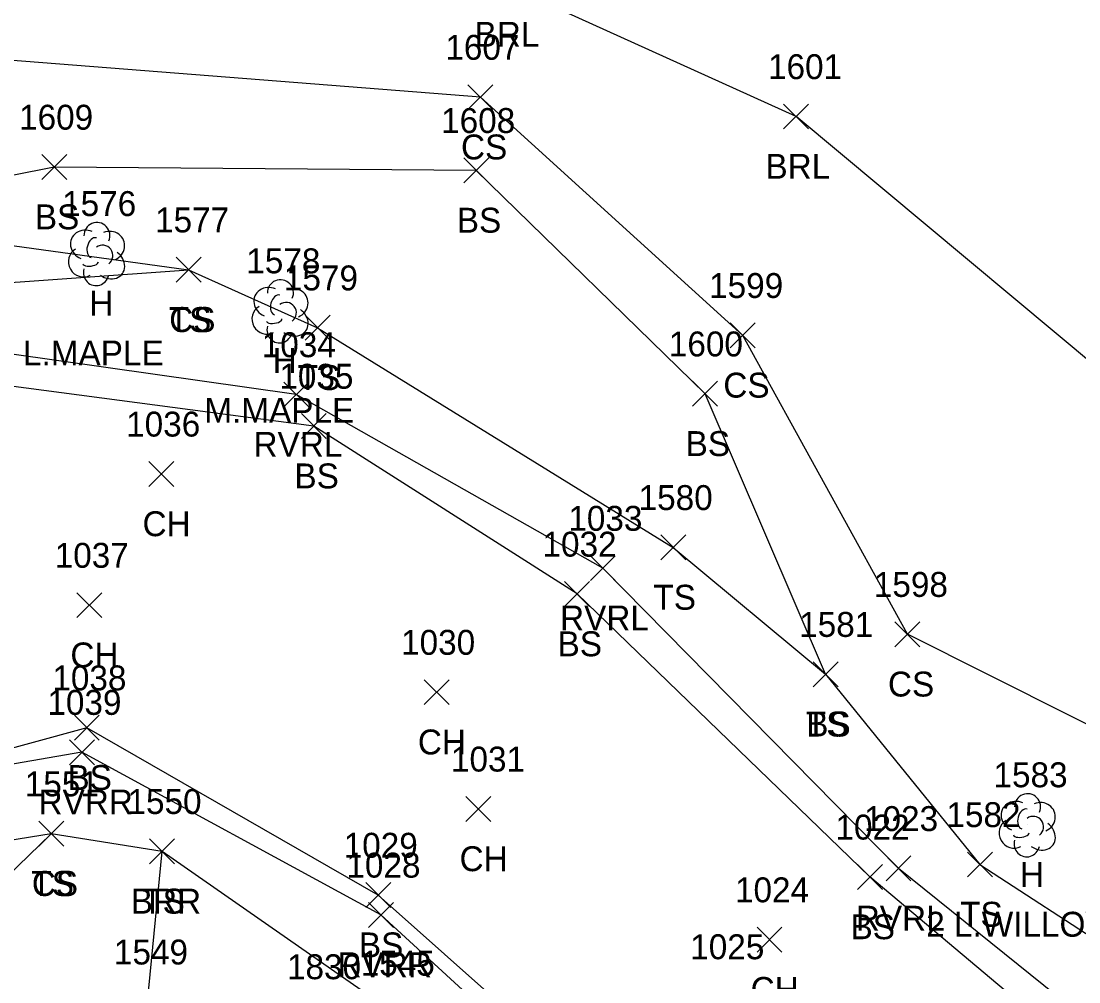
# Model space of a CAD drawing. Extents: x 1469310 to 1475157, y 493997 to 498873.
# Drawn here: x 1469623 to 1469708, y 498574.2 to 498651.4 of the extents above; entities that cross this region are included whole.
import ezdxf

# ---------------------------------------------------------------- set-up
doc = ezdxf.new("R2010")
doc.units = 0
for name, color, linetype in [('L_A', 7, 'Continuous'), ('L_C', 7, 'Continuous'), ('L_I', 7, 'Continuous'), ('L_TIC', 7, 'Continuous'), ('LABL', 7, 'Continuous'), ('LAWE', 7, 'Continuous'), ('LELB', 7, 'Continuous'), ('LTD', 7, 'Continuous')]:
    doc.layers.add(name, color=color, linetype=linetype)

msp = doc.modelspace()

# ---------------------------------------------------------------- linework, layer by layer
at = {"layer": 'L_TIC'}
for points in [[(1469658.92, 498644.282), (1469660.92, 498646.282)], [(1469660.92, 498644.282), (1469658.92, 498646.282)], [(1469684.262, 498642.727), (1469686.262, 498644.727)], [(1469686.262, 498642.727), (1469684.262, 498644.727)], [(1469624.704, 498638.67), (1469626.704, 498640.67)], [(1469626.704, 498638.67), (1469624.704, 498640.67)], [(1469658.583, 498638.402), (1469660.583, 498640.402)], [(1469660.583, 498638.402), (1469658.583, 498640.402)], [(1469635.49, 498630.421), (1469637.49, 498632.421)], [(1469637.49, 498630.421), (1469635.49, 498632.421)], [(1469635.49, 498630.421), (1469637.49, 498632.421)], [(1469637.49, 498630.421), (1469635.49, 498632.421)], [(1469645.843, 498625.766), (1469647.843, 498627.766)], [(1469647.843, 498625.766), (1469645.843, 498627.766)], [(1469679.981, 498625.156), (1469681.981, 498627.156)], [(1469681.981, 498625.156), (1469679.981, 498627.156)], [(1469644.136, 498620.402), (1469646.136, 498622.402)], [(1469646.136, 498620.402), (1469644.136, 498622.402)], [(1469676.953, 498620.464), (1469678.953, 498622.464)], [(1469678.953, 498620.464), (1469676.953, 498622.464)], [(1469645.545, 498617.868), (1469647.545, 498619.868)], [(1469647.545, 498617.868), (1469645.545, 498619.868)], [(1469633.302, 498614.028), (1469635.302, 498616.028)], [(1469635.302, 498614.028), (1469633.302, 498616.028)], [(1469674.4, 498608.126), (1469676.4, 498610.126)], [(1469676.4, 498608.126), (1469674.4, 498610.126)], [(1469668.748, 498606.461), (1469670.748, 498608.461)], [(1469670.748, 498606.461), (1469668.748, 498608.461)], [(1469666.675, 498604.387), (1469668.675, 498606.387)], [(1469668.675, 498604.387), (1469666.675, 498606.387)], [(1469627.511, 498603.492), (1469629.511, 498605.492)], [(1469629.511, 498603.492), (1469627.511, 498605.492)], [(1469693.201, 498601.154), (1469695.201, 498603.154)], [(1469695.201, 498601.154), (1469693.201, 498603.154)], [(1469686.639, 498597.943), (1469688.639, 498599.943)], [(1469688.639, 498597.943), (1469686.639, 498599.943)], [(1469686.639, 498597.943), (1469688.639, 498599.943)], [(1469688.639, 498597.943), (1469686.639, 498599.943)], [(1469655.408, 498596.505), (1469657.408, 498598.505)], [(1469657.408, 498596.505), (1469655.408, 498598.505)], [(1469627.321, 498593.647), (1469629.321, 498595.647)], [(1469629.321, 498593.647), (1469627.321, 498595.647)], [(1469626.93, 498591.682), (1469628.93, 498593.682)], [(1469628.93, 498591.682), (1469626.93, 498593.682)], [(1469658.757, 498587.13), (1469660.757, 498589.13)], [(1469660.757, 498587.13), (1469658.757, 498589.13)], [(1469624.46, 498585.142), (1469626.46, 498587.142)], [(1469626.46, 498585.142), (1469624.46, 498587.142)], [(1469624.46, 498585.142), (1469626.46, 498587.142)], [(1469626.46, 498585.142), (1469624.46, 498587.142)], [(1469633.36, 498583.722), (1469635.36, 498585.722)], [(1469635.36, 498583.722), (1469633.36, 498585.722)], [(1469633.36, 498583.722), (1469635.36, 498585.722)], [(1469635.36, 498583.722), (1469633.36, 498585.722)], [(1469692.491, 498582.351), (1469694.491, 498584.351)], [(1469694.491, 498582.351), (1469692.491, 498584.351)], [(1469699.03, 498582.669), (1469701.03, 498584.669)], [(1469701.03, 498582.669), (1469699.03, 498584.669)], [(1469690.198, 498581.668), (1469692.198, 498583.668)], [(1469692.198, 498581.668), (1469690.198, 498583.668)], [(1469650.721, 498580.21), (1469652.721, 498582.21)], [(1469652.721, 498580.21), (1469650.721, 498582.21)], [(1469650.931, 498578.614), (1469652.931, 498580.614)], [(1469652.931, 498578.614), (1469650.931, 498580.614)], [(1469682.129, 498576.632), (1469684.129, 498578.632)], [(1469684.129, 498576.632), (1469682.129, 498578.632)]]:
    msp.add_lwpolyline(points, dxfattribs=at)
at = {"layer": 'LABL'}
for points in [[(1469804.951, 498565.122), (1469764.815, 498561.657), (1469749.085, 498576.217), (1469733.116, 498600.55), (1469716.502, 498617.668), (1469685.262, 498643.727), (1469661.907, 498654.328), (1469615.65, 498657.999), (1469588.273, 498643.441), (1469563.61, 498633.273)], [(1469812.399, 498427.833), (1469789.823, 498450.509), (1469762.155, 498470.412), (1469730.759, 498496.59), (1469695.428, 498518.468), (1469668.132, 498535.818), (1469658.486, 498545.191), (1469647.104, 498565.825), (1469633.195, 498572.637), (1469634.36, 498584.722)]]:
    msp.add_lwpolyline(points, dxfattribs=at)
at = {"layer": 'LAWE'}
for points in [[(1469773.599, 498538.143), (1469743.152, 498547.619), (1469721.093, 498561.124), (1469693.491, 498583.351), (1469669.748, 498607.461), (1469645.136, 498621.402), (1469610.764, 498626.27), (1469594.257, 498621.311), (1469595.404, 498613.659), (1469596.705, 498614.177)], [(1469777.093, 498513.113), (1469746.487, 498519.646), (1469712.258, 498538.306), (1469693.077, 498549.784), (1469666.06, 498566.648), (1469651.931, 498579.614), (1469627.93, 498592.682), (1469614.452, 498590.358), (1469606.528, 498592.025), (1469606.275, 498594.975), (1469607.183, 498595.593)]]:
    msp.add_lwpolyline(points, dxfattribs=at)
at = {"layer": 'LELB'}
for points in [[(1469749.085, 498576.217), (1469720.606, 498588.908), (1469694.201, 498602.154), (1469680.981, 498626.156), (1469659.92, 498645.282), (1469619.31, 498648.468), (1469591.689, 498636.397), (1469573.01, 498624.242)], [(1469687.639, 498598.943), (1469677.953, 498621.464), (1469659.583, 498639.402), (1469625.704, 498639.67), (1469592.894, 498633.155), (1469579.511, 498624.432), (1469577.982, 498615.263)], [(1469600.588, 498604.32), (1469587.662, 498609.367), (1469585.469, 498618.104), (1469584.447, 498621.658), (1469592.042, 498627.254), (1469618.412, 498633.909), (1469636.49, 498631.421), (1469646.843, 498626.766), (1469675.4, 498609.126), (1469687.639, 498598.943), (1469700.03, 498583.669), (1469721.266, 498569.857), (1469752.353, 498551.496), (1469778.45, 498547.84), (1469808.958, 498549.067)], [(1469625.46, 498586.142), (1469619.296, 498585.147), (1469606.231, 498585.955), (1469602.337, 498593.71), (1469604.707, 498595.752), (1469602.628, 498599.074), (1469600.588, 498604.32), (1469596.556, 498609.811), (1469594.143, 498610.889), (1469587.662, 498609.367), (1469589.604, 498621.597), (1469618.042, 498630.111), (1469636.49, 498631.421)], [(1469772.295, 498536.699), (1469742.731, 498545.987), (1469719.144, 498559.139), (1469691.198, 498582.668), (1469667.675, 498605.387), (1469646.545, 498618.868), (1469610.656, 498623.611), (1469596.02, 498618.19), (1469597.153, 498614.345), (1469602.07, 498605.375)], [(1469781.028, 498516.12), (1469746.539, 498524.213), (1469713.591, 498540.942), (1469693.445, 498551.74), (1469667.941, 498566.775), (1469651.721, 498581.21), (1469628.321, 498594.647), (1469613.889, 498590.693), (1469608.413, 498591.74), (1469608.455, 498595.925), (1469602.07, 498605.375)], [(1469812.464, 498502.377), (1469771.643, 498507.322), (1469742.885, 498510.086), (1469696.566, 498535.255), (1469676.255, 498550.532), (1469652.996, 498571.738), (1469634.36, 498584.722), (1469625.46, 498586.142), (1469614.784, 498575.789), (1469604.978, 498569.723)]]:
    msp.add_lwpolyline(points, dxfattribs=at)
at = {"layer": 'LTD'}
for p, q in [((1469629.082, 498632.735), (1469629.082, 498632.735)), ((1469629.082, 498632.735), (1469629.082, 498632.735)), ((1469643.814, 498628.136), (1469643.814, 498628.136)), ((1469643.814, 498628.136), (1469643.814, 498628.136)), ((1469703.808, 498586.869), (1469703.808, 498586.869)), ((1469703.808, 498586.869), (1469703.808, 498586.869))]:
    msp.add_line(p, q, dxfattribs=at)
for centre in [(1469629.129, 498634.169), (1469643.861, 498629.57), (1469703.854, 498588.303)]:
    msp.add_arc(centre, 1.047, 335.52715, 180.95627, dxfattribs=at)
for centre, major_axis, ratio, start_param, end_param in [((1469628.291, 498633.402), (1.21, -0.512), 0.895232, 1.570796, 4.712389), ((1469628.874, 498633.193), (-0.208, -0.792), 0.645439, 3.141593, 6.283185), ((1469630.124, 498633.319), (-1.141, -0.483), 0.949671, 1.570796, 4.712389), ((1469629.582, 498632.568), (-0.5, 0.667), 0.989748, 3.141593, 6.283185), ((1469627.999, 498632.027), (0.584, -1.042), 0.959034, 3.141593, 6.283185), ((1469630.082, 498631.902), (-1.09, 0.792), 0.841452, 1.570796, 4.712389), ((1469629.083, 498631.235), (0.265, 1.061), 0.942809, 1.570796, 4.712389), ((1469628.624, 498631.985), (-0.625, -0.083), 0.423636, 0, 3.141593), ((1469643.022, 498628.803), (1.21, -0.512), 0.895232, 1.570796, 4.712389), ((1469644.855, 498628.72), (-1.141, -0.483), 0.949671, 1.570796, 4.712389), ((1469643.605, 498628.595), (-0.208, -0.792), 0.645439, 3.141593, 6.283185), ((1469644.314, 498627.97), (-0.5, 0.667), 0.989748, 3.141593, 6.283185), ((1469642.731, 498627.428), (0.584, -1.042), 0.959034, 3.141593, 6.283185), ((1469644.814, 498627.303), (-1.09, 0.792), 0.841452, 1.570796, 4.712389), ((1469643.356, 498627.386), (-0.625, -0.083), 0.423636, 0, 3.141593), ((1469643.814, 498626.636), (0.265, 1.061), 0.942809, 1.570796, 4.712389), ((1469703.016, 498587.535), (1.21, -0.512), 0.895232, 1.570796, 4.712389), ((1469703.599, 498587.327), (-0.208, -0.792), 0.645439, 3.141593, 6.283185), ((1469704.849, 498587.452), (-1.141, -0.483), 0.949671, 1.570796, 4.712389), ((1469704.308, 498586.702), (-0.5, 0.667), 0.989748, 3.141593, 6.283185), ((1469702.724, 498586.16), (0.584, -1.042), 0.959034, 3.141593, 6.283185), ((1469704.808, 498586.035), (-1.09, 0.792), 0.841452, 1.570796, 4.712389), ((1469703.808, 498585.369), (0.265, 1.061), 0.942809, 1.570796, 4.712389), ((1469703.349, 498586.119), (-0.625, -0.083), 0.423636, 0, 3.141593)]:
    msp.add_ellipse(centre, major_axis=major_axis, ratio=ratio, start_param=start_param, end_param=end_param, dxfattribs=at)

# ---------------------------------------------------------------- texts
at = {"layer": 'L_A'}
for s, p in [('BRL', (1469659.451, 498649.328)), ('CS', (1469658.361, 498640.282)), ('BRL', (1469682.805, 498638.727)), ('BS', (1469624.145, 498634.67)), ('BS', (1469658.024, 498634.402)), ('H', (1469628.515, 498627.735)), ('TS', (1469634.899, 498626.421)), ('CS', (1469634.931, 498626.421)), ('H', (1469643.247, 498623.136)), ('TS', (1469645.253, 498621.766)), ('CS', (1469679.422, 498621.156)), ('RVRL', (1469641.703, 498616.402)), ('BS', (1469676.394, 498616.464)), ('BS', (1469644.986, 498613.868)), ('CH', (1469632.79, 498610.028)), ('TS', (1469673.81, 498604.126)), ('RVRL', (1469666.315, 498602.461)), ('BS', (1469666.116, 498600.387)), ('CH', (1469626.999, 498599.492)), ('CS', (1469692.642, 498597.154)), ('TS', (1469686.048, 498593.943)), ('BS', (1469686.08, 498593.943)), ('CH', (1469654.896, 498592.505)), ('BS', (1469626.762, 498589.647)), ('RVRR', (1469624.442, 498587.682)), ('CH', (1469658.245, 498583.13)), ('TS', (1469623.869, 498581.142)), ('CS', (1469623.901, 498581.142)), ('H', (1469703.241, 498581.869)), ('BRR', (1469631.849, 498579.722)), ('TS', (1469632.77, 498579.722)), ('TS', (1469698.439, 498578.669)), ('BS', (1469689.639, 498577.668)), ('RVRL', (1469690.058, 498578.351)), ('BS', (1469650.162, 498576.21)), ('RVRR', (1469648.443, 498574.614)), ('CH', (1469681.617, 498572.632))]:
    msp.add_text(s, height=2, dxfattribs=at).set_placement(p)
at = {"layer": 'L_C'}
for s, p in [('L.MAPLE', (1469623.193, 498623.735)), ('M.MAPLE', (1469637.751, 498619.136)), ('2 L.WILLOW', (1469695.713, 498577.869))]:
    msp.add_text(s, height=2, dxfattribs=at).set_placement(p)
at = {"layer": 'L_I'}
for s, p in [('1607', (1469657.102, 498648.282)), ('1601', (1469683.01, 498646.727)), ('1609', (1469622.878, 498642.67)), ('1608', (1469656.764, 498642.402)), ('1576', (1469626.335, 498635.735)), ('1577', (1469633.797, 498634.421)), ('1577', (1469633.797, 498634.421)), ('1578', (1469641.121, 498631.136)), ('1579', (1469644.143, 498629.766)), ('1599', (1469678.281, 498629.156)), ('1034', (1469642.364, 498624.402)), ('1600', (1469675.048, 498624.464)), ('1035', (1469643.773, 498621.868)), ('1036', (1469631.475, 498618.028)), ('1580', (1469672.621, 498612.126)), ('1033', (1469666.977, 498610.461)), ('1032', (1469664.904, 498608.387)), ('1037', (1469625.739, 498607.492)), ('1598', (1469691.508, 498605.154)), ('1581', (1469685.513, 498601.943)), ('1581', (1469685.513, 498601.943)), ('1030', (1469653.55, 498600.505)), ('1038', (1469625.55, 498597.647)), ('1039', (1469625.151, 498595.682)), ('1031', (1469657.553, 498591.13)), ('1583', (1469701.115, 498589.869)), ('1551', (1469623.334, 498589.142)), ('1551', (1469623.334, 498589.142)), ('1550', (1469631.581, 498587.722)), ('1550', (1469631.581, 498587.722)), ('1023', (1469690.72, 498586.351)), ('1582', (1469697.337, 498586.669)), ('1022', (1469688.426, 498585.668)), ('1029', (1469648.941, 498584.21)), ('1028', (1469649.16, 498582.614)), ('1024', (1469680.358, 498580.632)), ('1025', (1469676.766, 498576.06)), ('1549', (1469630.494, 498575.637)), ('1830', (1469644.388, 498574.456)), ('1545', (1469650.303, 498574.738))]:
    msp.add_text(s, height=2, dxfattribs=at).set_placement(p)

doc.saveas('drawing.dxf')
